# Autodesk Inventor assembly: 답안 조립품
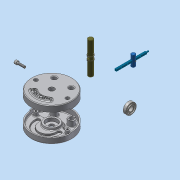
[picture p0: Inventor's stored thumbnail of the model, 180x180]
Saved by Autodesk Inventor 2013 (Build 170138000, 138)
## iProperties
Created: 2015-04
Part Number: 답안 조립품
Document SubType Name: Assembly
Designer: Administrator
Author: Administrator
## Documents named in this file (10)
- C:\Users\Administrator\Desktop\450406V1004\답안 조립품.iam
- C:\Users\Administrator\Desktop\450406V1004\M 10 x 35.ipt
- C:\Users\Administrator\Desktop\450406V1004\답안 본체.ipt
- C:\Users\Administrator\Desktop\450406V1004\덮개.ipt
- C:\Users\Administrator\Desktop\450406V1004\멈춤링.ipt
- C:\Users\Administrator\Desktop\450406V1004\베어링62_22.ipt
- C:\Users\Administrator\Desktop\450406V1004\슬라이더.ipt
- C:\Users\Administrator\Desktop\450406V1004\슬라이더2.ipt
- C:\Users\Administrator\Desktop\450406V1004\축.ipt
- C:\Users\Administrator\Desktop\450406V1004\평행핀.ipt
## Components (1 placed, 1 different names)
1. M 10 x 35:1
